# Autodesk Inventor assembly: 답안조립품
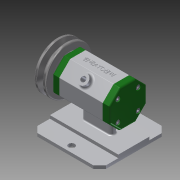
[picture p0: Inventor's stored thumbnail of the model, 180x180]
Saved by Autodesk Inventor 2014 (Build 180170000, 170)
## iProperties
Created: 2018-06
Part Number: 답안조립품
Document SubType Name: Assembly
Designer: kh
Author: kh
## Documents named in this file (15)
- C:\Users\kh\Desktop\480607V1010\답안조립품.iam
- C:\Users\kh\Desktop\480607V1010\본체.ipt
- C:\Users\kh\Desktop\480607V1010\축.ipt
- C:\Users\kh\Desktop\480607V1010\베어링 15x32x9.ipt
- C:\Users\kh\Desktop\480607V1010\뒤커버.ipt
- C:\Users\kh\Desktop\480607V1010\앞커버.ipt
- C:\Users\kh\Desktop\480607V1010\오일 실 15 25 7.ipt
- C:\Users\kh\Desktop\480607V1010\볼트 M4x12.ipt
- C:\Users\kh\Desktop\480607V1010\키 3x3x12.ipt
- 키 3x3x12.ipt
- C:\Users\kh\Desktop\480607V1010\V벨트풀리.ipt
- C:\Users\kh\Desktop\480607V1010\와셔 8x17.ipt
- C:\Users\kh\Desktop\480607V1010\스프링와셔 8.ipt
- C:\Users\kh\Desktop\480607V1010\너트 M8.ipt
- 너트 M8.ipt
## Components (1 placed, 1 different names)
1. V벨트풀리:1 — Insert:10, Mate:3, Insert:11
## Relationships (3: Insert 2, Mate 1)
- Insert:10: V벨트풀리:1
- Mate:3: V벨트풀리:1
- Insert:11: V벨트풀리:1
